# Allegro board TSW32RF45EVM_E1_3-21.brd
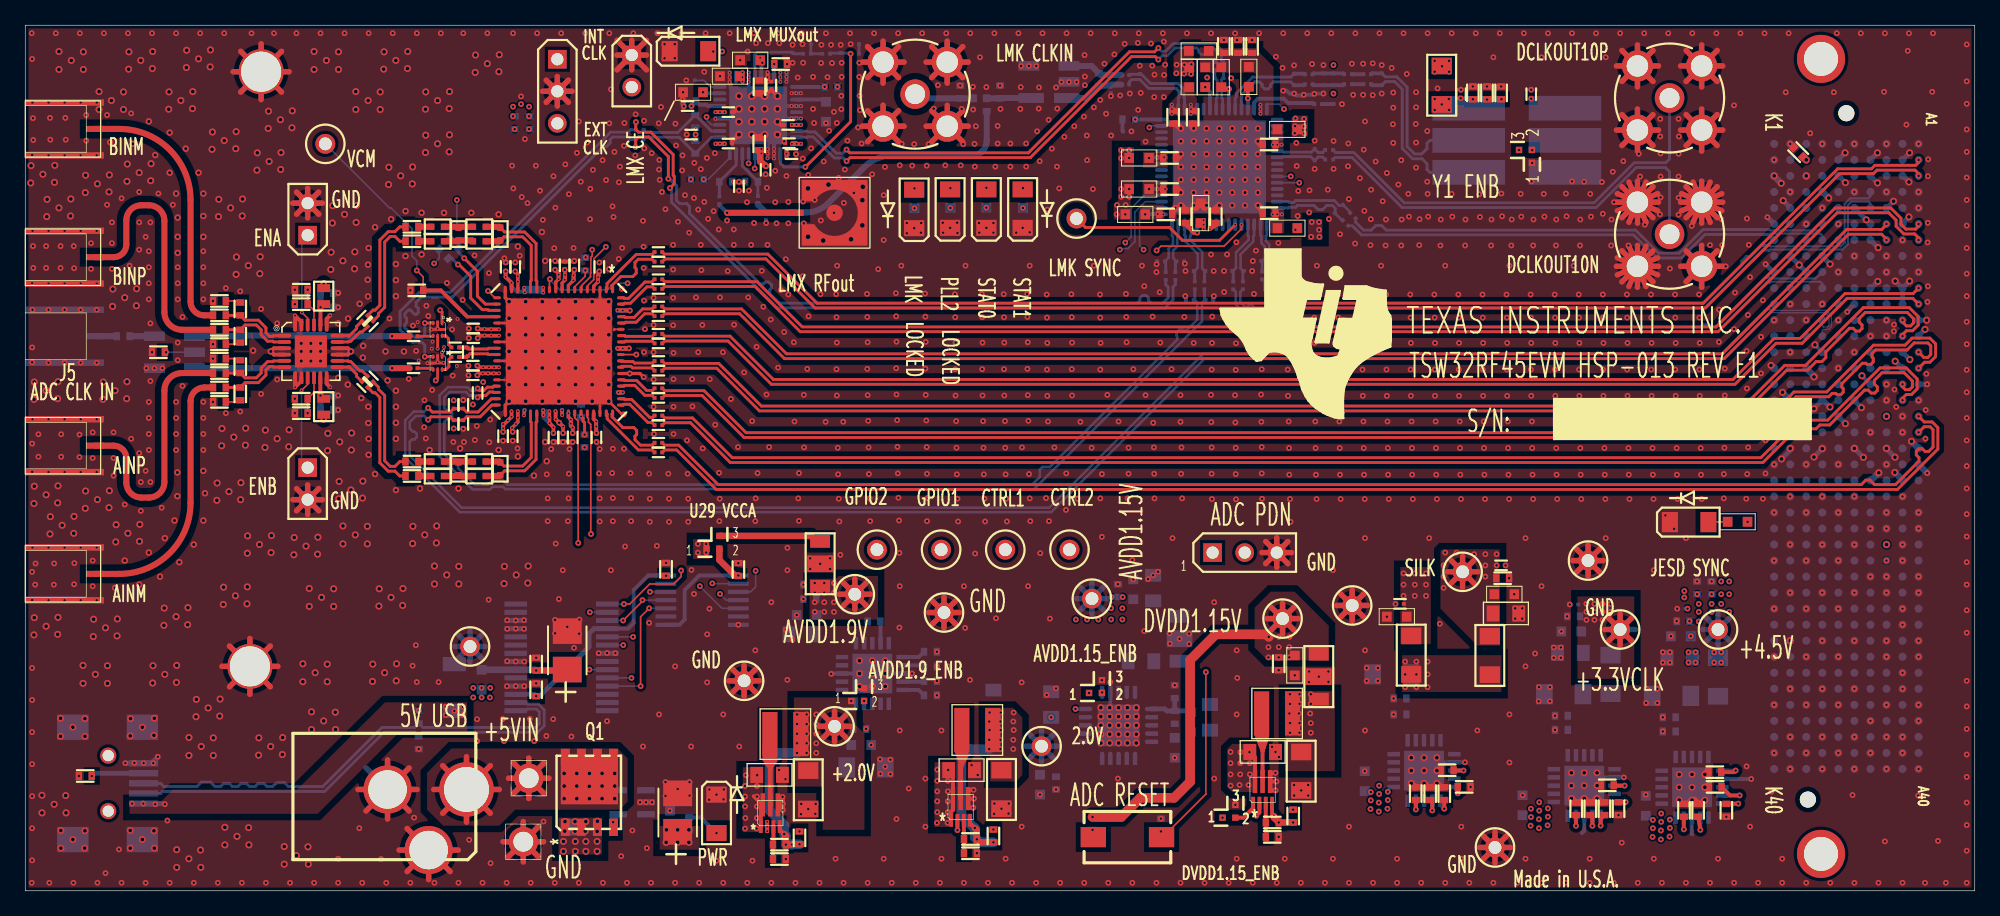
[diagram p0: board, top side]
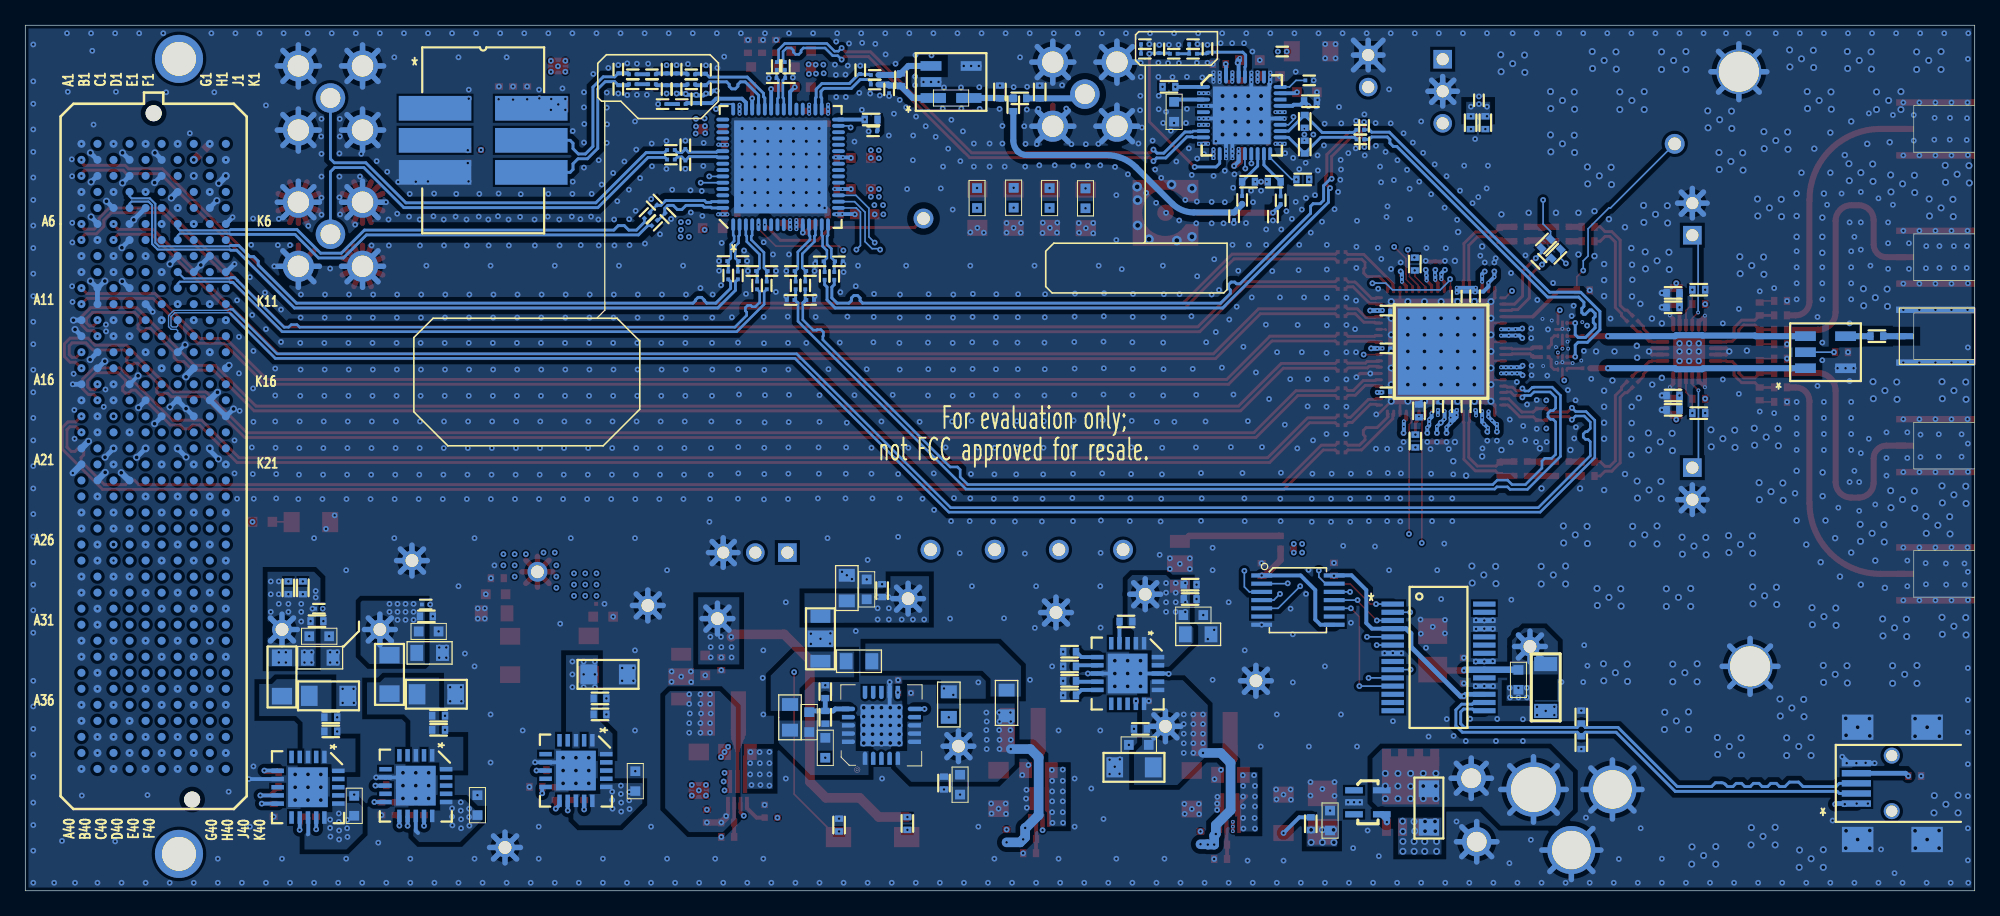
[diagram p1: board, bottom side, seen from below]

Outline 154.31 x 68.58 mm; copper layers: TOP, L2_GND, L3_PWR, L4_SIG, L5_GND, L6_PWR, L7_GND, BOTTOM. Coordinates in mm from the lower left corner of the outline.
Outline path: 0,68.58 0,0 154.31,0 154.31,68.58 0,68.58

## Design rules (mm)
net group CLK: nets CLKM CLKP
net group CLK_LAO: nets CLK_LAO_0M CLK_LAO_0P
net group CLKIN1: nets CLKIN1_N CLKIN1_P
net group DA0: nets DA0M DA0P
net group DA1: nets DA1M DA1P
net group DA2: nets DA2M DA2P
net group DA3: nets DA3M DA3P
net group DB0: nets DB0M DB0P
net group DB1: nets DB1M DB1P
net group DB2: nets DB2M DB2P
net group DB3: nets DB3M DB3P
net group DIFFPAIR9: nets GTXCLKM GTXCLKP
net group DP1: nets N19886018 N19886020
net group DP2: nets CLKLA_0M CLKLA_0P
net group DP3: nets N20235277 N20235286
net group DP4: nets N20015888 N20015984
net group DP5: nets SYSREF+ SYSREF-
net group DP6: nets AINM AINP
net group DP7: nets BINM BINP
net group DP8: nets LMX_OSCM LMX_OSCP
net group DP9: nets DA0_M DA0_P
net group DP10: nets DA1_M DA1_P
net group DP11: nets DA2_M DA2_P
net group DP12: nets DA3_M DA3_P
net group DP13: nets DB0_M DB0_P
net group DP14: nets DB1_M DB1_P
net group DP15: nets DB2_M DB2_P
net group DP16: nets DB3_M DB3_P
net group DP17: nets JESD_SYSREFM JESD_SYSREFP
net group DP18: nets USBDM USBDP
net group DP19: nets LMX_CLKM LMX_CLKP
net group FPGA_JESD_CLK: nets FPGA_JESD_CLKM FPGA_JESD_CLKP
net group FPGA_JESD_SYSREF: nets FPGA_JESD_SYSREFM FPGA_JESD_SYSREFP
net group INA: nets INA+ INA-
net group INB: nets INB+ INB-
net group OSC: nets OSCN OSCP
net group OSCIN: nets OSCINN OSCINP
net group OSCOUT: nets OSCOUTN OSCOUTP
net group OUTA: nets OUTA+ OUTA-
net group OUTB: nets OUTB+ OUTB-
net group SYNCB: nets SYNCBM SYNCBP
net group SYSREF: nets SYSREFM SYSREFP
net group TA: nets TA+ TA-
net group TB: nets TB+ TB-
net group Y2: nets Y2_N Y2_P

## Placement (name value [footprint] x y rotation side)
C1  .01uF  [0402]  21.84 47.62 0 bottom
C2  3.9pF  [0402_CUSTOM]  34.29 33.44 90 top
C3  1.6pF  [0402_CUSTOM]  37.59 33.44 90 top
C4  .1uF  [0402]  15.37 41.02 0 top
C5  .1uF  [0402]  15.37 39.88 0 top
C6  1.6pF  [0402_CUSTOM]  37.59 52.03 270 top
C8  .1uF  [0201]  91.03 48.72 270 bottom
C9  .1uF  [0201]  90.27 48.72 270 bottom
C10  3.9pF  [0402_CUSTOM]  34.29 52.03 270 top
C11  2200pF  [0402]  132.33 24 90 bottom
C12  .01uF  [0402]  133.48 24 90 bottom
C13  .1uF  [0201]  50.11 41.21 0 top
C14  .1uF  [0201]  50.11 41.97 0 top
C15  .1uF  [0201]  50.11 39.05 0 top
C16  .1uF  [0201]  50.11 39.81 0 top
C17  .1uF  [0201]  50.11 36.89 0 top
C18  .1uF  [0201]  50.11 37.66 0 top
C19  .1uF  [0201]  50.11 34.73 0 top
C20  .1uF  [0201]  50.11 35.5 0 top
C21  .1uF  [0201]  50.11 44.13 0 top
C22  .1uF  [0201]  50.11 43.37 0 top
C23  .1uF  [0201]  50.11 46.29 0 top
C24  .1uF  [0201]  50.11 45.53 0 top
C25  2200pF  [0402]  23.88 47.37 0 bottom
C26  .1uF  [0201]  50.11 48.45 0 top
C27  .1uF  [0201]  50.11 47.69 0 top
C28  .01uF  [0402]  7.75 43.94 0 bottom
C29  .01uF  [0402]  23.88 46.23 0 bottom
C30  .1uF  [0201]  50.11 50.61 0 top
C31  .1uF  [0201]  50.11 49.85 0 top
C32  2200pF  [0402]  23.88 39.24 0 bottom
C33  .1uF  [0402]  10.54 42.67 180 top
C34  .01uF  [0402]  23.88 38.1 0 bottom
C35  10uF  [0603]  128.27 6.73 90 bottom
C36  1uF  [0402]  131.29 6.38 90 top
C37  .1uF  [0201]  42.7 49.56 90 top
C38  .1uF  [0201]  41 47.09 270 bottom
C39  .1uF  [0201]  39.55 47.12 270 bottom
C40  .1uF  [0201]  38.02 49.43 90 top
C41  .1uF  [0201]  35.46 43.79 180 top
C42  .1uF  [0201]  35.43 41.61 180 top
C43  .1uF  [0201]  37.82 36.02 270 top
C44  .1uF  [0201]  39.52 38.38 90 bottom
C45  .1uF  [0201]  41 38.38 90 bottom
C46  .1uF  [0201]  41.81 35.92 270 top
C47  .1uF  [0201]  42.47 38.38 90 bottom
C48  .1uF  [0201]  41.94 49.56 90 top
C49  .1uF  [0201]  38.79 49.43 90 top
C50  .01uF  [0201]  35.46 44.55 180 top
C51  .01uF  [0201]  35.43 40.84 180 top
C52  .1uF  [0201]  38.58 36.02 270 top
C53  .1uF  [0201]  42.57 35.92 270 top
C54  .1uF  [0201]  45.44 49.43 90 top
C55  .1uF  [0201]  43.46 49.56 90 top
C56  .1uF  [0201]  43.33 35.92 270 top
C57  .1uF  [0201]  45.21 35.92 270 top
C58  .1uF  [0201]  46.58 39.5 180 bottom
C59  .1uF  [0201]  46.58 42.98 180 bottom
C60  .1uF  [0201]  46.58 45.97 180 bottom
C61  .1uF  [0402]  30.99 47.57 180 top
C62  .1uF  [0402]  130.12 12.62 180 bottom
C63  1uF  [0402]  130.12 13.74 180 bottom
C64  47uF  [1206]  130.3 15.44 180 bottom
C65  33uF  [0805]  130.96 18.47 180 bottom
C66  10uF  [0603]  131.04 20.17 180 bottom
C67  .1uF  [0201]  98.66 48.75 270 bottom
C68  .1uF  [0201]  119.2 63.12 90 top
C69  .1uF  [0201]  97.9 48.75 270 bottom
C70  .68uF  [0402]  87.35 61.11 180 bottom
C71  3900pF  [0201]  102.34 62.33 0 bottom
C72  47pF  [0201]  101.19 62.71 90 bottom
C73  .01uF  [0201]  87.07 63.88 0 bottom
C74  .01uF  [0201]  87.07 64.64 0 bottom
C75  .1uF  [0201]  88.21 65.02 270 bottom
C76  .1uF  [0402]  131.22 21.36 180 bottom
C77  .1uF  [0201]  113.64 63.12 270 top
C78  100pF  [0402]  114.58 63.22 270 top
C79  2200pF  [0402]  115.7 63.22 270 top
C80  10pF  [0402]  116.81 63.22 270 top
C81  .1uF  [0201]  104.7 64.69 180 bottom
C82  .1uF  [0201]  101.59 64.69 180 bottom
C83  .1uF  [0201]  100.43 65.05 270 bottom
C84  .1uF  [0201]  104.7 63.91 180 bottom
C85  .1uF  [0201]  101.59 63.9 180 bottom
C86  12pF  [0201]  100.43 63.52 90 bottom
C87  1uF  [0402]  90.86 61.29 90 top
C88  .1uF  [0402]  94.23 53.42 270 top
C89  0.01uF  [0402]  92.41 61.29 90 top
C90  1uF  [0402]  90.27 53.59 180 top
C91  1uF  [0402]  90.58 55.6 180 top
C92  1uF  [0402]  90.58 58.06 180 top
C93  1uF  [0402]  94.87 66.9 270 top
C94  .1uF  [0402]  95.99 66.9 270 top
C95  0.01uF  [0402]  97.1 66.9 270 top
C96  .1uF  [0402]  91.85 53.42 90 top
C97  10uF  [0603]  93.04 53.7 90 top
C98  1uF  [0402]  98.45 59.13 0 top
C99  1uF  [0402]  98.45 53.7 0 top
C100  .01uF  [0201]  131.06 22.35 180 bottom
C101  4.7uF  [TANT_B]  42.9 19.05 90 top
C102  .1uF  [0402]  40.44 17.96 90 top
C103  47pF  [0402]  31.14 11.73 270 bottom
C104  47pF  [0402]  31.14 13.77 90 bottom
C105  .1uF  [0402]  40.44 15.93 90 top
C110  .1uF  [0402]  15.37 44.45 0 top
C111  .1uF  [0402]  15.37 45.59 0 top
C114  .01uF  [0402]  21.84 37.85 0 bottom
C121  10uF  [0805]  74.11 9.56 0 top
C122  1uF  [0402]  81.58 8.53 270 bottom
C126  2.2uF  [0603]  80.31 8.41 270 bottom
C156  10uF  [0603]  118.52 6.78 90 bottom
C157  .1uF  [0402]  121.59 12.75 180 bottom
C158  1uF  [0402]  121.59 13.87 180 bottom
C159  47uF  [1206]  121.77 15.57 180 bottom
C160  33uF  [0805]  122.3 18.85 180 bottom
C161  10uF  [0603]  122.38 20.55 180 bottom
C162  .01uF  [0201]  122.61 22.68 180 bottom
C163  .1uF  [0402]  122.56 21.74 180 bottom
C166  1uF  [0402]  122.76 6.5 90 top
C170  .1uF  [0201]  103.2 58.7 0 bottom
C171  .1uF  [0201]  103.2 57.94 0 bottom
C172  47uF  [TANT_B]  51.64 6.2 90 top
C173  10uF  [0603]  51.03 5.56 90 bottom
C183  10uF  [0805]  58.91 9.18 0 top
C184  22uF  [1206]  61.98 8 270 top
C185  33uF  [0805]  61.47 20.32 180 bottom
C186  10uF  [0603]  61.85 21.84 180 bottom
C187  1uF  [0402]  62.1 23.11 180 bottom
C188  .1uF  [0402]  62.1 24.26 180 bottom
C189  47uF  [1206]  66.55 9.78 0 bottom
C190  10uF  [0603]  66.17 11.56 0 bottom
C191  1uF  [0402]  66.04 12.83 0 bottom
C193  .47uF  [0603]  92.25 13.36 90 bottom
C194  33uF  [0805]  89.28 23.98 90 bottom
C195  10uF  [0603]  87.7 23.88 90 bottom
C196  1uF  [0402]  86.48 23.78 90 bottom
C197  10uF  [0603]  90.98 11.33 270 bottom
C198  4.7uF  [0805]  81.2 14.76 90 bottom
C203  10uF  [0805]  97.94 11 0 top
C204  22uF  [1206]  100.99 9.47 270 top
C368  .1uF  [0402]  56.45 25.45 90 top
C369  .1uF  [0402]  50.72 25.47 270 top
C372  .1uF  [0201]  30.73 43.94 0 top
C373  .1uF  [0201]  30.73 41.4 0 top
C376  22uF  [1206]  77.27 8.03 270 top
C377  10uF  [0603]  100.48 17.86 270 top
C378  1uF  [0402]  99.21 17.98 270 top
C379  10uF  [0603]  108.56 21.72 180 top
C380  .01uF  [0201]  108.81 22.73 180 top
C381  10uF  [0603]  117.07 23.5 0 top
C382  .1uF  [0402]  116.94 24.77 0 top
C383  .01uF  [0201]  116.81 25.78 0 top
C384  33uF  [0805]  117.2 21.97 0 top
C385  47uF  [1206]  108.18 17.14 180 bottom
C386  10uF  [0603]  106.02 8.69 90 bottom
C387  1uF  [0402]  110.06 7.7 90 top
C388  .1uF  [0402]  108.81 13.97 180 bottom
C389  1uF  [0402]  108.81 15.24 180 bottom
C390  .1uF  [0201]  55.65 61.7 180 top
C391  .1uF  [0201]  60.45 59.23 0 top
C392  .1uF  [0201]  60.38 60.68 180 top
C393  .1uF  [0201]  60.66 58.37 0 top
C394  .047uF  [0201]  65.68 66.32 0 bottom
C395  560pF  [0201]  64.54 66.68 90 bottom
C396  .1uF  [0201]  58.6 57.12 270 top
C397  .1uF  [0201]  55.65 59.21 0 top
C398  1uF  [0402]  58.09 59.18 270 top
C399  .1uF  [0201]  52.43 62.18 180 top
C400  1uF  [0402]  52.58 62.56 0 bottom
C401  .1uF  [0201]  59.05 63.8 270 top
C402  1uF  [0402]  58.12 63.7 90 top
C403  10uF  [0603]  63.37 61.72 90 bottom
C404  1uF  [0402]  59.79 65.51 180 top
C405  10uF  [0603]  52.86 63.27 0 top
C406  10uF  [0603]  57.38 65.81 0 top
C407  10uF  [0603]  55.78 64.54 0 top
C408  100pF  [0201]  52.7 59.92 180 top
C409  100pF  [0201]  48.64 60.3 180 bottom
C410  100pF  [0201]  48.62 59.54 180 bottom
C411  100pF  [0201]  56.49 55.83 270 top
C412  100pF  [0201]  57.99 54.74 270 bottom
C413  100pF  [0201]  54.94 54.71 270 bottom
C418  .1uF  [0201]  94.18 65.35 90 bottom
C419  .1uF  [0201]  94.82 65.35 90 bottom
C420  6800pF  [0201]  61.87 67.08 180 bottom
C421  6800pF  [0201]  60.73 66.7 90 bottom
C428  .1uF  [0201]  39.24 62.64 90 bottom
C429  .1uF  [0201]  34.04 43.05 0 top
C430  .1uF  [0201]  34.04 42.29 0 top
C431  .1uF  [0201]  48.34 60.6 90 bottom
C432  .1uF  [0201]  48.31 59.23 270 bottom
C433  .01uF  [0402]  30.61 52.61 0 top
C434  .01uF  [0402]  30.61 51.46 0 top
C435  .01uF  [0402]  30.61 32.86 0 top
C436  .01uF  [0402]  30.61 34.01 0 top
C437  .01uF  [0402]  15.37 43.31 0 top
C438  .01uF  [0402]  15.37 46.74 0 top
C439  .01uF  [0402]  15.37 38.73 0 top
C440  .01uF  [0402]  15.37 42.16 0 top
D1  LED GREEN  [LED_1206]  76.07 54.05 270 top
D2  LED GREEN  [LED_1206]  78.94 54.05 270 top
D3  LED GREEN  [LED_1206]  70.36 54.03 270 top
D4  LED GREEN  [LED_1206]  73.2 54.05 270 top
D5  LED GREEN  [LED_1206]  131.7 29.21 180 top
D6  LED GREEN  [LED_1206]  54.71 6.1 90 top
D7  LED GREEN  [LED_1206]  52.53 66.52 180 top
F1  FUSE 10A 63V FAST  [1206]  43.21 6.55 270 bottom
FB1  120 OHM @ 100MHz  [1206]  112.12 63.83 90 top
FB2  120 OHM  [0603]  92.13 64.47 270 top
FB3  120 OHM  [0603]  87.86 53.59 0 top
FB4  120 OHM  [0603]  88.16 55.6 0 top
FB5  120 OHM  [0603]  88.16 58.06 0 top
FB6  120 OHM  [0603]  92.89 66.55 0 top
FB7  120 OHM  [0603]  93.4 64.47 270 top
FB8  120 OHM  [0603]  94.67 64.47 270 top
FB9  120 OHM  [0603]  96.85 64.49 270 top
FB10  120 OHM  [0603]  99.89 60.33 180 top
FB11  120 OHM  [0603]  99.9 52.5 180 top
FB12  1K OHM @ 100MHz  [1806]  33.96 16.1 270 bottom
FB13  120 OHM @ 100MHz  [1206]  133.99 16.94 90 bottom
FB14  120 OHM @ 100MHz  [1206]  109.7 18.67 90 top
FB15  120 OHM @ 100MHz  [1206]  115.93 18.64 90 top
FB16  120 OHM @ 100MHz  [1206]  125.48 17.14 90 bottom
FB17  27uF  [1206_BEAD_NFM31P]  91.36 19.96 90 bottom
FB19  27uF  [1206_BEAD_NFM31P]  102.39 16.97 90 top
FB20  27uF  [1206_BEAD_NFM31P]  62.92 25.91 90 top
HS1  COPPER PIN FIN HEAT SINK  [HEATSINK_270X270]  42.24 42.72 180 bottom
J1  CONN, MMSP-3805-LD-EDGE  [SMA-MSSP-4848-EDGE_MICRO]  5.21 35.27 0 top
J2  CONN, MMSP-3805-LD-EDGE  [SMA-MSSP-4848-EDGE_MICRO]  5.21 25.11 0 top
J3  CONN, MMSP-3805-LD-EDGE  [SMA-MSSP-4848-EDGE_MICRO]  5.21 50.2 0 top
J4  CONN, MMSP-3805-LD-EDGE  [SMA-MSSP-4848-EDGE_MICRO]  5.21 60.36 0 top
J5  CONN, MMSP-3805-LD-EDGE  [SMA-MSSP-4848-EDGE_MICRO]  5.21 43.94 0 bottom
J6  SMP_PCB_SMT  [SMP_B120]  64.06 53.72 270 top
J7  SMA_THVT_REC  [SMA_THVT_312X312]  70.43 63.12 0 top
J8  CONN, JACK, PWR, MINI, R/A, TH  [CON_RAPC722_JACK_THVT_3]  31.8 8.03 270 top
J9  SMA_THVT_REC  [SMA_THVT_312X312]  130.15 52.02 0 top
J10  CON, SMVT, HS, FIELD ARRAY, 400POS, MALE  [CON_SMVT_40X10_SEAM_MTG]  144.14 34.42 90 bottom
J11  CONN, USB MINI AB, SMT  [CON_SMRT_USBMNE20_F]  5.92 8.51 0 bottom
J13  SMA_THVT_REC  [SMA_THVT_312X312]  130.15 62.81 0 top
JP1  HDR, THVT, 3POS  [HDR_THVT_1X3_100_M]  93.98 26.8 90 top
JP2  HEADER_1x2_100_430L  [HDR_THVT_1X2_100_M]  48.01 66.22 0 top
JP3  HDR, THVT, 3POS  [HDR_THVT_1X3_100_M]  42.11 65.89 0 top
JP4  JUMPER_1X2_100  [HDR_THVT_1X2_100_M]  22.35 51.94 180 top
JP5  JUMPER_1X2_100  [HDR_THVT_1X2_100_M]  22.35 33.53 0 top
L1  .47uH  [IND_SM_XFL4015]  60.17 12.41 0 top
L2  .47uH  [IND_SM_XFL4015]  75.36 12.74 0 top
L3  .47uH  [IND_SM_XFL4015]  99.09 14.05 0 top
L4  5.1nH  [IND_0603]  23.62 47.12 270 top
L5  2nH  [0402_CUSTOM]  32.64 32.86 0 top
L6  2nH  [0402_CUSTOM]  32.64 34.01 0 top
L7  4.9nH  [0402_CUSTOM]  35.94 32.86 0 top
L8  2nH  [0402_CUSTOM]  32.64 52.61 0 top
L9  2nH  [0402_CUSTOM]  32.64 51.46 0 top
L11  4.9nH  [0402_CUSTOM]  35.94 52.61 0 top
L12  4.9nH  [0402_CUSTOM]  35.94 51.46 0 top
L13  4.9nH  [0402_CUSTOM]  35.94 34.01 0 top
L14  5.1nH  [IND_0603]  23.62 38.35 90 top
MT1  STANDOFF, FEMALE, 4-40 X 1 3/16", AL  [MFG125_PLATED]  18.67 64.9 0 top
MT2  STANDOFF, FEMALE, 4-40 X 1 3/16", AL  [MFG125_PLATED]  17.78 17.78 0 top
NOREF  -  []  0 0 90 top
NOREF#2  -  []  242.57 11.43 0 top
NOREF#3  -  []  116.51 3.91 0 top
NOREF#4  -  []  0 58.52 90 top
NOREF#5  -  []  494.89 162.18 0 top
NOREF#6  -  []  0 0 90 top
NOREF#7  -  []  101.19 -25.65 0 top
NOREF#8  -  []  0 68.58 0 top
NOREF#9  -  []  0 0 90 top
NOREF#10  -  []  10.77 37.72 0 top
NOREF#11  -  []  0 0 90 top
NOREF#12  -  []  0 0 0 top
NOREF#13  -  []  726.8 113.13 0 top
NOREF#14  -  []  161.32 -26.49 0 top
NOREF#15  -  []  -106.07 -149.22 0 top
NOREF#16  -  []  0 0 0 top
NOREF#17  -  []  145.54 -11.73 0 top
NOREF#18  -  []  314.12 44.43 0 top
NOREF#19  -  []  -95.38 325.27 0 top
NOREF#20  -  []  0 0 90 top
NOREF#21  -  []  0 0 90 top
NOREF#22  -  []  100.33 -4.45 180 bottom
Q1  CSD18532Q5  [SON_Q5B_8]  44.65 7.8 90 top
R1  90.9  [0402]  17.02 41.53 90 top
R2  4.99k  [0402]  21.84 46.48 0 top
R3  4.99k  [0402]  21.84 47.62 180 top
R4  24.9  [0201]  26.87 40.11 315 top
R5  24.9  [0201]  27.31 40.55 315 top
R6  90.9  [0402]  17.02 43.94 270 top
R7  4.99k  [0402]  21.84 38.99 0 top
R8  4.99k  [0402]  21.84 37.85 180 top
R9  24.9  [0201]  26.87 45.36 45 top
R10  24.9  [0201]  27.31 44.92 45 top
R11  0  [0402]  132.41 6.38 270 top
R12  0  [0402]  134.65 6.38 90 top
R13  0  [0402]  133.76 8.23 0 top
R14  0  [0402]  133.73 9.4 0 top
R26  100  [0201]  35.03 42.68 90 top
R29  100  [0201]  35.8 39.44 90 top
R31  0  [0402]  44.27 35.64 90 bottom
R32  10K  [0402]  43.99 38.02 90 bottom
R33  1K  [0402]  84.48 5.33 270 bottom
R34  1K  [0402]  44.32 49.66 270 bottom
R35  10K  [0402]  89.89 5.21 90 bottom
R40  100  [0201]  34.5 49.86 45 bottom
R47  39K  [0201]  87.2 60.17 0 bottom
R48  0  [0201]  96.38 47.97 270 bottom
R49  0  [0201]  95.62 47.97 270 bottom
R50  240  [0201]  95.24 49.11 180 bottom
R51  240  [0201]  96.76 49.11 0 bottom
R52  240  [0201]  97.52 49.9 180 bottom
R53  240  [0201]  99.05 49.9 0 bottom
R54  620  [0201]  103.86 62.33 0 bottom
R55  49.9  [0201]  85.93 63.5 270 bottom
R56  0  [0603]  81.03 62.81 0 bottom
R57  18  [0402]  75.58 62.79 0 bottom
R58  292  [0402]  74.01 63.29 90 bottom
R59  292  [0402]  77.16 63.29 90 bottom
R60  100  [0402]  84.99 64.26 90 bottom
R63  120  [0201]  91.43 49.87 0 bottom
R64  120  [0201]  89.9 49.87 180 bottom
R65  100  [0201]  93.33 47.97 270 bottom
R66  100  [0201]  92.57 47.97 270 bottom
R67  200  [0201]  93.71 49.11 0 bottom
R68  200  [0201]  92.19 49.11 180 bottom
R69  100  [0201]  92.18 46.81 180 bottom
R70  100  [0201]  93.73 46.81 0 bottom
R71  130  [0201]  103.54 65.07 270 bottom
R72  100  [0201]  106.22 64.69 180 bottom
R73  82  [0201]  107.37 65.07 90 bottom
R74  49.9  [0201]  102.75 65.07 90 bottom
R75  0  [0201]  105.08 53.49 315 bottom
R76  130  [0201]  103.54 63.52 90 bottom
R77  240  [0201]  104.51 54.56 45 bottom
R78  240  [0201]  103.44 53.48 225 bottom
R79  0  [0201]  104.5 52.91 315 bottom
R80  100  [0201]  106.22 63.91 180 bottom
R81  82  [0201]  107.37 63.53 270 bottom
R82  49.9  [0201]  102.75 63.52 270 bottom
R84  750  [0603]  76.07 54.91 270 bottom
R85  750  [0603]  78.97 54.89 270 bottom
R86  750  [0603]  70.38 54.86 270 bottom
R87  750  [0603]  73.23 54.89 270 bottom
R88  750  [0603]  135.53 29.24 0 top
R89  0  [0402]  140.34 58.52 135 top
R95  0  [0603]  36.12 16.71 90 bottom
R96  0  [0402]  4.75 9.09 0 top
R124  0  [0402]  123.88 6.5 270 top
R125  0  [0402]  124.99 6.5 270 top
R126  0  [0402]  126.11 6.5 90 top
R127  0  [0402]  125.22 8.36 0 top
R132  287K  [0402]  59.69 3.66 180 top
R133  1K  [0402]  52.55 5.31 90 bottom
R134  162K  [0402]  59.69 2.51 0 top
R136  1M  [0402]  61.28 4.19 90 top
R137  36.5K  [0402]  67.18 21.34 0 bottom
R138  0  [0402]  71.65 18.94 180 bottom
R139  0  [0402]  71.65 17.77 180 bottom
R140  0  [0402]  71.65 16.63 180 bottom
R141  0  [0402]  71.65 15.49 180 bottom
R143  2.4K  [0402]  90.98 13.74 90 bottom
R145  4.75K  [0402]  90.98 15.77 90 bottom
R146  82K  [0402]  98.7 5.41 180 top
R147  162K  [0402]  98.7 4.27 0 top
R148  1M  [0402]  100.36 5.92 90 top
R151  240  [0201]  102.06 57.56 270 bottom
R152  240  [0201]  102.06 59.08 90 bottom
R153  1M  [0402]  76.63 4.34 90 top
R154  124K  [0402]  74.81 4.1 180 top
R155  162K  [0402]  74.81 2.97 0 top
R157  0  [0805]  76.63 14.88 270 bottom
R158  0  [0805]  93.78 13.74 270 bottom
R159  0  [0805]  88.32 18.19 180 bottom
R164  0  [0402]  33.12 50.47 315 bottom
R165  0  [0402]  33.93 51.28 315 bottom
R166  182  [0201]  33.91 36.98 90 top
R167  182  [0201]  33.91 38.51 270 top
R168  68  [0201]  34.67 36.98 270 top
R169  68  [0201]  34.67 38.51 90 top
R170  0  [0402]  111.2 7.7 270 top
R171  0  [0402]  112.55 9.55 0 top
R172  0  [0402]  112.32 7.7 270 top
R173  0  [0402]  113.89 8.23 180 top
R174  150  [0201]  65.68 67.08 180 bottom
R175  49.9  [0402]  53.04 60.96 270 bottom
R176  49.9  [0402]  53.04 58.93 90 bottom
R177  49.9  [0402]  57.48 56.18 180 bottom
R178  49.9  [0402]  55.45 56.18 0 bottom
R179  680  [0201]  52.68 64.21 0 bottom
R180  240  [0201]  95.15 64.39 0 bottom
R181  240  [0201]  93.85 64.39 180 bottom
R182  0  [0201]  63.4 66.32 180 bottom
R183  12  [0201]  61.87 66.32 180 bottom
R184  0  [0402]  53.19 56.36 180 bottom
R185  680  [0201]  54.81 66.5 0 bottom
R186  12k  [0402]  63.78 63.7 0 bottom
R187  49.9  [0201]  55.55 53.42 90 bottom
R188  10K  [0402]  38.73 60.86 270 bottom
R189  10K  [0402]  39.9 60.86 270 bottom
R191  0  [0402]  76.1 62.28 270 bottom
R192  49.9  [0201]  58.62 53.44 90 bottom
R193  80.6  [0402]  17.02 46.1 90 top
R194  80.6  [0402]  17.02 39.37 270 top
SJP1  SOLDER JUMPER, 0402  [SMD_JUMPER_L_0402]  119.25 58.19 90 top
SJP2  SOLDER JUMPER, 0402  [SMD_JUMPER_L_0402]  65.89 15.04 0 top
SJP3  SOLDER JUMPER, 0402  [SMD_JUMPER_L_0402]  84.71 15.67 0 top
SJP4  SOLDER JUMPER, 0402  [SMD_JUMPER_L_0402]  95.28 5.79 0 top
SJP5  SOLDER JUMPER, 0402  [SMD_JUMPER_L_0402]  54.43 27.1 0 top
SW1  SWITCH, SMT, PUSHBUTTON  [SW_SMVT_SPST_EVQPJX_2]  87.24 4.25 0 top
T5  ETC1-1-13  [TFMR_5_150X150_50]  11.81 42.67 0 bottom
T6  TC1-1-13M+  [TFMR_5_150X150_50]  81.03 64.08 0 bottom
TP1  RED  [TP_THVT_060_RND]  133.99 20.7 0 top
TP2  RED  [TP_THVT_060_RND]  23.75 59.18 0 top
TP3  YELLOW  [TP_THVT_060_RND]  72.49 27.03 0 top
TP4  RED  [TP_THVT_060_RND]  35.2 19.35 0 top
TP5  RED  [TP_THVT_060_RND]  99.52 21.56 0 top
TP6  BLK  [TP_THVT_060_RND]  105.03 22.61 0 top
TP7  YELLOW  [TP_THVT_060_RND]  67.41 27.03 0 top
TP8  YELLOW  [TP_THVT_060_RND]  77.57 27.03 0 top
TP9  YELLOW  [TP_THVT_060_RND]  82.65 27.03 0 top
TP10  RED  [TP_THVT_060_RND]  113.77 25.27 0 top
TP11  BLK  [TP_THVT_060_RND]  116.33 3.43 0 top
TP12  RED  [TP_THVT_060_RND]  126.24 20.7 0 top
TP13  RED  [TP_THVT_060_RND]  80.44 11.46 0 top
TP14  BLK  [TP_THVT_060_RND]  56.9 16.64 0 top
TP15  RED  [TP_THVT_060_RND]  64.06 13.03 0 top
TP16  YELLOW  [TP_THVT_060_RND]  83.21 53.26 0 top
TP17  Testloop_Red  [TESTPOINT_62DIA]  39.85 8.92 0 top
TP18  Testloop_Black  [TESTPOINT_62DIA]  39.42 3.89 0 top
TP19  BLK  [TP_THVT_060_RND]  123.7 26.16 0 top
TP20  RED  [TP_THVT_060_RND]  65.66 23.5 0 top
TP21  BLK  [TP_THVT_060_RND]  72.72 22.05 0 top
TP22  RED  [TP_THVT_060_RND]  84.43 23.14 90 top
U1  ADC32RF45_72QFN  [QFN_72_10MMX10MM_0P50MM_PWRPAD]  42.24 42.74 270 top
U2  LMH3401  [QFN24_RGE_RTW_P5MM]  22.61 42.74 0 top
U3  LMK04828  [QFN_64_360X360_0P50MM_PWRPAD]  94.52 57.35 90 bottom
U4  TPS7A4700  [QFN_20_199X199_0P65MM]  131.93 8.2 270 bottom
U5  FT245RL  [SSOP_28_413X220_26]  42.44 18.49 180 bottom
U7  MASW_009444  [PDFN_6_P35MM]  32.64 41.81 270 top
U8  MASW_009444  [PDFN_6_P35MM]  32.64 44.48 270 top
U9  TPS7A4700  [QFN_20_199X199_0P65MM]  110.72 9.53 270 bottom
U10  LMX2582_LM2592  [QFN40_RTA_RTB_RHA]  58.01 61.44 180 bottom
U11  TPS62085  [QFN_RLT_7]  74.03 6.64 90 top
U12  TPS7A4700  [QFN_20_199X199_0P65MM]  123.39 8.33 270 bottom
U13  TXB0104  [TSSOP14]  53.57 23.03 180 bottom
U14  TPS62085  [QFN_RLT_7]  58.97 6.14 90 top
U15  TPS2400  [DBV5]  48.03 7.01 180 bottom
U16  TPS7A7200  [QFN_20_199X199_0P65MM]  67.05 17.21 270 bottom
U17  TPS74201/QFN20  [QFN20_RGW_P65PITCH]  86.54 13.11 90 bottom
U18  TPS62085  [QFN_RLT_7]  97.94 8 90 top
Y1  122.88MHz  [VCXO_6_CUSTOM]  118.06 59.46 180 bottom

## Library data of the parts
C1 C28 C72 C114 C437-C440 = CAP NP_0: tolerance: 5%
C2 C10 = CAP_0402_3.9pF
C3 C6 = CAP_0402_1.8pF
C4 C5 C110 C111 = CAP_0603_0.1uF_H: tolerance: 10%
C8 C9 C67 C69 C83 C87-C96 C98 C99 C170 C171 C368 C369 C390-C393 C396 C397 C399 C401 C418 C419 = CAPACITOR_NP_1: tolerance: 10%
C11 C25 C32 = CAP_0402_2200pF
C12 C29 C34 C433-C436 = CAP_0402_0.01uF
C13-C24 C26 C27 C30 C31 = CAP_0201_0.1uF: tolerance: 10%
C33 C62 C76 C157 C163 C188 C382 C388 = CAP0603: tolerance: 10%
C35 C121 C156 C173 C183 C187 C190 C196 C197 C203 C378 C386 C403 C405-C407 = CAP NP_1: tolerance: 10%
C36 C63 C68 C70 C71 C82 C85 C102 C105 C122 C158 C166 C191 C387 C389 C394 C395 C398 C400 C402 C404 C420 C421 = CAP NP_0: tolerance: 10%
C37-C49 C52-C61 C372 C373 C428-C432 = CAP0402_0: tolerance: 10%
C50 C51 = CAP0402_0: tolerance: +/-10%
C64 C159 C189 C385 = CAP NP_0: tolerance: 20%
C65 C160 C185 C186 C194 C195 C377 C384 = CAP0201_0: tolerance: 20%
C66 C161 C379 C381 = CAP0201_0: tolerance: 10%
C73 C74 = CAP_0402_0.01uF_H: tolerance: 10%
C75 = CAP_0402_0.1uF: tolerance: 10%
C77 C81 C84 = CAP_0402_0.1uF_H: tolerance: 10%
C78 C408-C413 = CAP_0603_100pF_H
C79 = CAP_0402_2200pF_H
C80 = CAP_0402_10pF_H
C86 = CAPACITOR_NP_1: tolerance: 2%
C97 = CAP NP_2: tolerance: 10%
C100 C162 C380 C383 = CAP0402_0: tolerance: 10V
C101 = CAP_TANT_B_4.7uF_10V
C103 C104 = CAP0603: tolerance: 1%
C126 = CAP_0603_2.2uF
C172 = CAP POL-B_0: tolerance: 10%
C184 C204 C376 = CAP: tolerance: 10%
C193 C198 = CAP_0603_.47uF
D1-D5 D7 = LED
D6 = LED_GREEN_0
F1 = FUSE_0
FB1-FB16 = FERRITE_BEAD_0402_H
FB17 FB19 FB20 = BEAD_NFM31P
HS1 = HEATSINK_270x270
J1-J5 = CON_LD_EDGE_MMSP_3805_M
J6 = SMP_PLUG_SMT
J7 J9 J13 = SMA-THVT_142-0701-201_REC
J8 = CONN JACK PWR
J10 = CON_SMVT_40X10_ASP-134487-01
J11 = USB_MINI_AB_MNE20-5G5P10
JP1 JP3 SJP1-SJP5 = SMD_JUMPER_1x3
JP2 = HDR_2x1_100
JP4 JP5 = JUMPER_1X2_100
L1-L3 = CHOKE
L4 L14 = IND_0603_H_0
L5-L9 L11-L13 = IND_0402_H_0
MT1 MT2 = MOUNTING_HOLE
Q1 = CSD18532Q5B
R1 R6 R166-R169 R193 R194 = Res_0402_49.9
R2 R3 R7 R8 = Res_0402_4.99K
R4 R5 R9 R10 R72 R80 = Res_0402_100_H
R11-R14 R124-R127 R138-R141 R170-R173 = R: tolerance: 5%
R26 R29 = Res_0201_200_H: tolerance: 1%
R31 = Res_0402_Zero_DNI
R32 R33 R35 R47 R54 R174 R188 R189 = R_1: tolerance: 1%
R34 = RES0603: tolerance: 1%
R40 = Res_0201_H: tolerance: 1%
R48 R49 R65 R66 R75 R79 R157-R159 R182 = Res_0402_Zero_H_DNI
R50-R53 R63 R64 R67 R68 R77 R78 R151 R152 R180 R181 = Res_0402_249
R55 R175-R179 R185 R187 R192 = Res_0402_49.9: tolerance: 1%
R56 R95 = Res_0603_Zero_DNI
R57 R183 R186 = Res_0402_18
R58 R59 = Res_0402_270
R60 R69 R70 = Res_0603_100
R71 R73 R74 R76 R81 R82 = RESISTOR_0: tolerance: 1%
R84-R88 = RESISTOR_0
R89 = Res_0402_Zero
R96 R164 R165 R184 R191 = R
R132 R146 R154 = Res_0603_Zero_H
R133 = Res_0402_1k: tolerance: 1%
R134 R136 R147 R148 R153 R155 = R: tolerance: 1%
R137 = Res_0402_Zero_H
R143 = Res_0603_12.4k
R145 = Res_0603_10k
SW1 = SPST_EVQ-PJ
T5 = BALUN_ETC1-1-13
T6 = TFMR_5_TC1-1-13M+
TP1 TP3 TP7-TP10 TP12 TP16 TP20 TP22 = TESTPOINT_BLUE
TP2 TP4 = TESTPOINT_RED
TP5 TP13 TP15 = TESTLOOP_RED
TP6 TP11 TP14 TP19 TP21 = TESTPOINT_BLK
TP17 TP18 = TESTLOOP_BLACK
U1 = ADC32RF4X_72QFN
U2 = LMH3404
U3 = LMK04828
U4 U9 U12 = TPS7A4700
U5 = FT245RL
U7 U8 = RF_SWITCH_MASW_009444
U10 = LMX2582_LM2592
U11 U14 U18 = TPS62085/62086/62087
U13 = TXS0104E: Tolerance: ***; User Part Number: ***
U15 = TPS2400
U16 = TPS7A7300
U17 = TPS74201/QFN20
Y1 = OSC_SM_6_TCO-2100-SERIES_2

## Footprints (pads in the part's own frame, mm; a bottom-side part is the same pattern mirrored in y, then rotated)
0201
  rect 0.305x0.305 smd: 1(-0.305,0) 2(0.305,0)
0402
  rect 0.508x0.635 smd: 1(-0.508,0) 2(0.508,0)
0402_CUSTOM
  rect 0.508x0.508 smd: 1(-0.508,0) 2(0.508,0)
0603
  rect 0.762x0.787 smd: 1(-0.787,0) 2(0.787,0)
0805
  rect 1.016x1.27 smd: 1(-1.016,0) 2(1.016,0)
1206
  rect 1.321x1.6 smd: 1(-1.524,0) 2(1.524,0)
1206_BEAD_NFM31P
  rect 1.016x1.575 smd: 1(-1.778,0) 3(1.778,0)
  rect 1.321x2.032 smd: 2(0,0)
1806
  rect 1.118x1.829 smd: 1(-1.854,0) 2(1.854,0)
CON_RAPC722_JACK_THVT_3
  round 4.318 hole 3.556: 1(0,3.124)
  round 3.81 hole 3.048: 2(0,-3.124) 3(4.801,0.127)
CON_SMRT_USBMNE20_F
  round 1.27 hole 0.889 unplated: (0.65,-2.2) (0.65,2.2)
  rect 2.311x0.508 smd: 1(3.45,1.6) 2(3.45,0.8) 3(3.45,0) 4(3.45,-0.8) 5(3.45,-1.6)
  rect 2.489x2.007 smd: 6(-2.15,-4.45) 7(3.35,-4.45) 8(3.35,4.45) 9(-2.15,4.45)
CON_SMVT_40X10_SEAM_MTG
  round 3.81 hole 2.692: (-31.496,-2.007) (31.496,-2.007)
  round 1.27 hole 1.27 unplated: (-27.191,-3.048) (27.191,0)
  round 0.635 smd: A1(24.765,5.715) A2(23.495,5.715) A3(22.225,5.715) A4(20.955,5.715) A5(19.685,5.715) A6(18.415,5.715) A7(17.145,5.715) A8(15.875,5.715) A9(14.605,5.715) A10(13.335,5.715) A11(12.065,5.715) A12(10.795,5.715) A13(9.525,5.715) A14(8.255,5.715) A15(6.985,5.715) A16(5.715,5.715) A17(4.445,5.715) A18(3.175,5.715) A19(1.905,5.715) A20(0.635,5.715) A21(-0.635,5.715) A22(-1.905,5.715) A23(-3.175,5.715) A24(-4.445,5.715) A25(-5.715,5.715) A26(-6.985,5.715) A27(-8.255,5.715) A28(-9.525,5.715) A29(-10.795,5.715) A30(-12.065,5.715) A31(-13.335,5.715) A32(-14.605,5.715) A33(-15.875,5.715) A34(-17.145,5.715) A35(-18.415,5.715) A36(-19.685,5.715) A37(-20.955,5.715) A38(-22.225,5.715) A39(-23.495,5.715) A40(-24.765,5.715) B1(24.765,4.445) B2(23.495,4.445) B3(22.225,4.445) B4(20.955,4.445) B5(19.685,4.445) B6(18.415,4.445) B7(17.145,4.445) B8(15.875,4.445) B9(14.605,4.445) B10(13.335,4.445) B11(12.065,4.445) B12(10.795,4.445) B13(9.525,4.445) B14(8.255,4.445) B15(6.985,4.445) B16(5.715,4.445) B17(4.445,4.445) B18(3.175,4.445) B19(1.905,4.445) B20(0.635,4.445) B21(-0.635,4.445) B22(-1.905,4.445) B23(-3.175,4.445) B24(-4.445,4.445) B25(-5.715,4.445) B26(-6.985,4.445) B27(-8.255,4.445) B28(-9.525,4.445) B29(-10.795,4.445) B30(-12.065,4.445) B31(-13.335,4.445) B32(-14.605,4.445) B33(-15.875,4.445) B34(-17.145,4.445) B35(-18.415,4.445) B36(-19.685,4.445) B37(-20.955,4.445) B38(-22.225,4.445) B39(-23.495,4.445) B40(-24.765,4.445) C1(24.765,3.175) C2(23.495,3.175) C3(22.225,3.175) C4(20.955,3.175) C5(19.685,3.175) C6(18.415,3.175) C7(17.145,3.175) C8(15.875,3.175) C9(14.605,3.175) C10(13.335,3.175) C11(12.065,3.175) C12(10.795,3.175) C13(9.525,3.175) C14(8.255,3.175) C15(6.985,3.175) C16(5.715,3.175) C17(4.445,3.175) C18(3.175,3.175) C19(1.905,3.175) C20(0.635,3.175) C21(-0.635,3.175) C22(-1.905,3.175) C23(-3.175,3.175) C24(-4.445,3.175) C25(-5.715,3.175) C26(-6.985,3.175) C27(-8.255,3.175) C28(-9.525,3.175) C29(-10.795,3.175) C30(-12.065,3.175) C31(-13.335,3.175) C32(-14.605,3.175) C33(-15.875,3.175) C34(-17.145,3.175) C35(-18.415,3.175) C36(-19.685,3.175) C37(-20.955,3.175) C38(-22.225,3.175) C39(-23.495,3.175) C40(-24.765,3.175) D1(24.765,1.905) D2(23.495,1.905) D3(22.225,1.905) D4(20.955,1.905) D5(19.685,1.905) D6(18.415,1.905) D7(17.145,1.905) D8(15.875,1.905) D9(14.605,1.905) D10(13.335,1.905) D11(12.065,1.905) D12(10.795,1.905) D13(9.525,1.905) D14(8.255,1.905) D15(6.985,1.905) D16(5.715,1.905) D17(4.445,1.905) D18(3.175,1.905) D19(1.905,1.905) D20(0.635,1.905) D21(-0.635,1.905) D22(-1.905,1.905) D23(-3.175,1.905) D24(-4.445,1.905) D25(-5.715,1.905) D26(-6.985,1.905) D27(-8.255,1.905) D28(-9.525,1.905) D29(-10.795,1.905) D30(-12.065,1.905) D31(-13.335,1.905) D32(-14.605,1.905) D33(-15.875,1.905) D34(-17.145,1.905) D35(-18.415,1.905) D36(-19.685,1.905) D37(-20.955,1.905) D38(-22.225,1.905) D39(-23.495,1.905) D40(-24.765,1.905) E1(24.765,0.635) E2(23.495,0.635) E3(22.225,0.635) E4(20.955,0.635) E5(19.685,0.635) E6(18.415,0.635) E7(17.145,0.635) E8(15.875,0.635) E9(14.605,0.635) E10(13.335,0.635) E11(12.065,0.635) E12(10.795,0.635) E13(9.525,0.635) E14(8.255,0.635) E15(6.985,0.635) E16(5.715,0.635) E17(4.445,0.635) E18(3.175,0.635) E19(1.905,0.635) E20(0.635,0.635) E21(-0.635,0.635) E22(-1.905,0.635) E23(-3.175,0.635) E24(-4.445,0.635) E25(-5.715,0.635) E26(-6.985,0.635) E27(-8.255,0.635) E28(-9.525,0.635) E29(-10.795,0.635) E30(-12.065,0.635) E31(-13.335,0.635) E32(-14.605,0.635) E33(-15.875,0.635) E34(-17.145,0.635) E35(-18.415,0.635) E36(-19.685,0.635) E37(-20.955,0.635) E38(-22.225,0.635) E39(-23.495,0.635) E40(-24.765,0.635) F1(24.765,-0.635) F2(23.495,-0.635) F3(22.225,-0.635) F4(20.955,-0.635) F5(19.685,-0.635) F6(18.415,-0.635) F7(17.145,-0.635) F8(15.875,-0.635) F9(14.605,-0.635) F10(13.335,-0.635) F11(12.065,-0.635) F12(10.795,-0.635) F13(9.525,-0.635) F14(8.255,-0.635) F15(6.985,-0.635) F16(5.715,-0.635) F17(4.445,-0.635) F18(3.175,-0.635) F19(1.905,-0.635) F20(0.635,-0.635) F21(-0.635,-0.635) F22(-1.905,-0.635) F23(-3.175,-0.635) F24(-4.445,-0.635) F25(-5.715,-0.635) F26(-6.985,-0.635) F27(-8.255,-0.635) F28(-9.525,-0.635) F29(-10.795,-0.635) F30(-12.065,-0.635) F31(-13.335,-0.635) F32(-14.605,-0.635) F33(-15.875,-0.635) F34(-17.145,-0.635) F35(-18.415,-0.635) F36(-19.685,-0.635) F37(-20.955,-0.635) F38(-22.225,-0.635) F39(-23.495,-0.635) F40(-24.765,-0.635) G1(24.765,-1.905) G2(23.495,-1.905) G3(22.225,-1.905) G4(20.955,-1.905) G5(19.685,-1.905) G6(18.415,-1.905) G7(17.145,-1.905) G8(15.875,-1.905) G9(14.605,-1.905) G10(13.335,-1.905) G11(12.065,-1.905) G12(10.795,-1.905) G13(9.525,-1.905) G14(8.255,-1.905) G15(6.985,-1.905) G16(5.715,-1.905) G17(4.445,-1.905) G18(3.175,-1.905) G19(1.905,-1.905) G20(0.635,-1.905) G21(-0.635,-1.905) G22(-1.905,-1.905) G23(-3.175,-1.905) G24(-4.445,-1.905) G25(-5.715,-1.905) G26(-6.985,-1.905) G27(-8.255,-1.905) G28(-9.525,-1.905) G29(-10.795,-1.905) G30(-12.065,-1.905) G31(-13.335,-1.905) G32(-14.605,-1.905) G33(-15.875,-1.905) G34(-17.145,-1.905) G35(-18.415,-1.905) G36(-19.685,-1.905) G37(-20.955,-1.905) G38(-22.225,-1.905) G39(-23.495,-1.905) G40(-24.765,-1.905) H1(24.765,-3.175) H2(23.495,-3.175) H3(22.225,-3.175) H4(20.955,-3.175) H5(19.685,-3.175) H6(18.415,-3.175) H7(17.145,-3.175) H8(15.875,-3.175) H9(14.605,-3.175) H10(13.335,-3.175) H11(12.065,-3.175) H12(10.795,-3.175) H13(9.525,-3.175) H14(8.255,-3.175) H15(6.985,-3.175) H16(5.715,-3.175) H17(4.445,-3.175) H18(3.175,-3.175) H19(1.905,-3.175) H20(0.635,-3.175) H21(-0.635,-3.175) H22(-1.905,-3.175) H23(-3.175,-3.175) H24(-4.445,-3.175) H25(-5.715,-3.175) H26(-6.985,-3.175) H27(-8.255,-3.175) H28(-9.525,-3.175) H29(-10.795,-3.175) H30(-12.065,-3.175) H31(-13.335,-3.175) H32(-14.605,-3.175) H33(-15.875,-3.175) H34(-17.145,-3.175) H35(-18.415,-3.175) H36(-19.685,-3.175) H37(-20.955,-3.175) H38(-22.225,-3.175) H39(-23.495,-3.175) H40(-24.765,-3.175) J1(24.765,-4.445) J2(23.495,-4.445) J3(22.225,-4.445) J4(20.955,-4.445) J5(19.685,-4.445) J6(18.415,-4.445) J7(17.145,-4.445) J8(15.875,-4.445) J9(14.605,-4.445) J10(13.335,-4.445) J11(12.065,-4.445) J12(10.795,-4.445) J13(9.525,-4.445) J14(8.255,-4.445) J15(6.985,-4.445) J16(5.715,-4.445) J17(4.445,-4.445) J18(3.175,-4.445) J19(1.905,-4.445) J20(0.635,-4.445) J21(-0.635,-4.445) J22(-1.905,-4.445) J23(-3.175,-4.445) J24(-4.445,-4.445) J25(-5.715,-4.445) J26(-6.985,-4.445) J27(-8.255,-4.445) J28(-9.525,-4.445) J29(-10.795,-4.445) J30(-12.065,-4.445) J31(-13.335,-4.445) J32(-14.605,-4.445) J33(-15.875,-4.445) J34(-17.145,-4.445) J35(-18.415,-4.445) J36(-19.685,-4.445) J37(-20.955,-4.445) J38(-22.225,-4.445) J39(-23.495,-4.445) J40(-24.765,-4.445) K1(24.765,-5.715) K2(23.495,-5.715) K3(22.225,-5.715) K4(20.955,-5.715) K5(19.685,-5.715) K6(18.415,-5.715) K7(17.145,-5.715) K8(15.875,-5.715) K9(14.605,-5.715) K10(13.335,-5.715) K11(12.065,-5.715) K12(10.795,-5.715) K13(9.525,-5.715) K14(8.255,-5.715) K15(6.985,-5.715) K16(5.715,-5.715) K17(4.445,-5.715) K18(3.175,-5.715) K19(1.905,-5.715) K20(0.635,-5.715) K21(-0.635,-5.715) K22(-1.905,-5.715) K23(-3.175,-5.715) K24(-4.445,-5.715) K25(-5.715,-5.715) K26(-6.985,-5.715) K27(-8.255,-5.715) K28(-9.525,-5.715) K29(-10.795,-5.715) K30(-12.065,-5.715) K31(-13.335,-5.715) K32(-14.605,-5.715) K33(-15.875,-5.715) K34(-17.145,-5.715) K35(-18.415,-5.715) K36(-19.685,-5.715) K37(-20.955,-5.715) K38(-22.225,-5.715) K39(-23.495,-5.715) K40(-24.765,-5.715)
DBV5
  rect 1.4x0.5 smd: 1(-1.1,0.95) 2(-1.1,0) 3(-1.1,-0.95) 4(1.1,-0.95) 5(1.1,0.95)
HDR_THVT_1X2_100_M
  rect 1.473x1.473 hole 0.965: 1(0,0)
  round 1.473 hole 0.965: 2(0,-2.54)
HDR_THVT_1X3_100_M
  rect 1.473x1.473 hole 0.965: 1(0,0)
  round 1.473 hole 0.965: 2(0,-2.54) 3(0,-5.08)
HEATSINK_270X270
  rect 6.858x6.858 smd: 1(0,0)
IND_0603
  rect 0.635x1.016 smd: 1(-0.635,0) 2(0.635,0)
IND_SM_XFL4015
  rect 1.2x3.5 smd: 1(-1.225,0) 2(1.225,0)
LED_1206
  rect 1.27x1.6 smd: 1(-1.524,0) 2(1.524,0)
MFG125_PLATED
  round 3.556 hole 3.175: 1(0,0)
PDFN_6_P35MM
  custom 0.045x0.045 smd: 1(-0.5,0.35) 2(-0.5,0) 3(-0.5,-0.35) 4(0.5,-0.35) 5(0.5,0) 6(0.5,0.35)
QFN20_RGW_P65PITCH
  custom 0.09x0.09 smd: 1(-2.607,1.3) 2(-2.607,0.65) 3(-2.607,0) 4(-2.607,-0.65) 5(-2.607,-1.3) 6(-1.3,-2.607) 7(-0.65,-2.607) 8(0,-2.607) 9(0.65,-2.607) 10(1.3,-2.607) 11(2.607,-1.3) 12(2.607,-0.65) 13(2.607,0) 14(2.607,0.65) 15(2.607,1.3) 16(1.3,2.607) 17(0.65,2.607) 18(0,2.607) 19(-0.65,2.607) 20(-1.3,2.607)
  rect 3.302x3.302 smd: 21(0,0)
QFN24_RGE_RTW_P5MM
  custom 0.076x0.076 smd: 1(-2.07,1.25) 2(-2.07,0.75) 3(-2.07,0.25) 4(-2.07,-0.25) 5(-2.07,-0.75) 6(-2.07,-1.25) 7(-1.25,-2.07) 8(-0.75,-2.07) 9(-0.25,-2.07) 10(0.25,-2.07) 11(0.75,-2.07) 12(1.25,-2.07) 13(2.07,-1.25) 14(2.07,-0.75) 15(2.07,-0.25) 16(2.07,0.25) 17(2.07,0.75) 18(2.07,1.25) 19(1.25,2.07) 20(0.75,2.07) 21(0.25,2.07) 22(-0.25,2.07) 23(-0.75,2.07) 24(-1.25,2.07)
  rect 2.54x2.54 smd: 25(0,0)
QFN40_RTA_RTB_RHA
  custom 0.076x0.076 smd: 1(-3.025,2.25) 2(-3.025,1.75) 3(-3.025,1.25) 4(-3.025,0.75) 5(-3.025,0.25) 6(-3.025,-0.25) 7(-3.025,-0.75) 8(-3.025,-1.25) 9(-3.025,-1.75) 10(-3.025,-2.25) 11(-2.25,-3.025) 12(-1.75,-3.025) 13(-1.25,-3.025) 14(-0.75,-3.025) 15(-0.25,-3.025) 16(0.25,-3.025) 17(0.75,-3.025) 18(1.25,-3.025) 19(1.75,-3.025) 20(2.25,-3.025) 21(3.025,-2.25) 22(3.025,-1.75) 23(3.025,-1.25) 24(3.025,-0.75) 25(3.025,-0.25) 26(3.025,0.25) 27(3.025,0.75) 28(3.025,1.25) 29(3.025,1.75) 30(3.025,2.25) 31(2.25,3.025) 32(1.75,3.025) 33(1.25,3.025) 34(0.75,3.025) 35(0.25,3.025) 36(-0.25,3.025) 37(-0.75,3.025) 38(-1.25,3.025) 39(-1.75,3.025) 40(-2.25,3.025)
  rect 4.572x4.572 smd: 41(0,0)
QFN_20_199X199_0P65MM
  rect 0.991x0.356 smd: 1(-2.4,1.3) 2(-2.4,0.65) 3(-2.4,0) 4(-2.4,-0.65) 5(-2.4,-1.3) 11(2.4,-1.3) 12(2.4,-0.65) 13(2.4,0) 14(2.4,0.65) 15(2.4,1.3)
  rect 0.356x0.991 smd: 6(-1.3,-2.4) 7(-0.65,-2.4) 8(0,-2.4) 9(0.65,-2.4) 10(1.3,-2.4) 16(1.3,2.4) 17(0.65,2.4) 18(0,2.4) 19(-0.65,2.4) 20(-1.3,2.4)
  rect 3.15x3.15 smd: 21(0,0)
QFN_64_360X360_0P50MM_PWRPAD
  oval 1.016x0.305 smd: 1(-4.58,3.753) 2(-4.58,3.252) 3(-4.58,2.752) 4(-4.58,2.252) 5(-4.58,1.751) 6(-4.58,1.251) 7(-4.58,0.751) 8(-4.58,0.25) 9(-4.58,-0.25) 10(-4.58,-0.751) 11(-4.58,-1.251) 12(-4.58,-1.751) 13(-4.58,-2.252) 14(-4.58,-2.752) 15(-4.58,-3.252) 16(-4.58,-3.753) 33(4.58,-3.753) 34(4.58,-3.252) 35(4.58,-2.752) 36(4.58,-2.252) 37(4.58,-1.751) 38(4.58,-1.251) 39(4.58,-0.751) 40(4.58,-0.25) 41(4.58,0.25) 42(4.58,0.751) 43(4.58,1.251) 44(4.58,1.751) 45(4.58,2.252) 46(4.58,2.752) 47(4.58,3.252) 48(4.58,3.753)
  oval 0.305x1.016 smd: 17(-3.753,-4.58) 18(-3.252,-4.58) 19(-2.752,-4.58) 20(-2.252,-4.58) 21(-1.751,-4.58) 22(-1.251,-4.58) 23(-0.751,-4.58) 24(-0.25,-4.58) 25(0.25,-4.58) 26(0.751,-4.58) 27(1.251,-4.58) 28(1.751,-4.58) 29(2.252,-4.58) 30(2.752,-4.58) 31(3.252,-4.58) 32(3.753,-4.58) 49(3.753,4.58) 50(3.252,4.58) 51(2.752,4.58) 52(2.252,4.58) 53(1.751,4.58) 54(1.251,4.58) 55(0.751,4.58) 56(0.25,4.58) 57(-0.25,4.58) 58(-0.751,4.58) 59(-1.251,4.58) 60(-1.751,4.58) 61(-2.252,4.58) 62(-2.752,4.58) 63(-3.252,4.58) 64(-3.753,4.58)
  rect 7.366x7.366 smd: 65(0,0)
QFN_72_10MMX10MM_0P50MM_PWRPAD
  oval 0.6x0.24 smd: 1(-4.9,4.25) 2(-4.9,3.75) 3(-4.9,3.25) 4(-4.9,2.75) 5(-4.9,2.25) 6(-4.9,1.75) 7(-4.9,1.25) 8(-4.9,0.75) 9(-4.9,0.25) 10(-4.9,-0.25) 11(-4.9,-0.75) 12(-4.9,-1.25) 13(-4.9,-1.75) 14(-4.9,-2.25) 15(-4.9,-2.75) 16(-4.9,-3.25) 17(-4.9,-3.75) 18(-4.9,-4.25) 37(4.9,-4.25) 38(4.9,-3.75) 39(4.9,-3.25) 40(4.9,-2.75) 41(4.9,-2.25) 42(4.9,-1.75) 43(4.9,-1.25) 44(4.9,-0.75) 45(4.9,-0.25) 46(4.9,0.25) 47(4.9,0.75) 48(4.9,1.25) 49(4.9,1.75) 50(4.9,2.25) 51(4.9,2.75) 52(4.9,3.25) 53(4.9,3.75) 54(4.9,4.25)
  oval 0.24x0.6 smd: 19(-4.25,-4.9) 20(-3.75,-4.9) 21(-3.25,-4.9) 22(-2.75,-4.9) 23(-2.25,-4.9) 24(-1.75,-4.9) 25(-1.25,-4.9) 26(-0.75,-4.9) 27(-0.25,-4.9) 28(0.25,-4.9) 29(0.75,-4.9) 30(1.25,-4.9) 31(1.75,-4.9) 32(2.25,-4.9) 33(2.75,-4.9) 34(3.25,-4.9) 35(3.75,-4.9) 36(4.25,-4.9) 55(4.25,4.9) 56(3.75,4.9) 57(3.25,4.9) 58(2.75,4.9) 59(2.25,4.9) 60(1.75,4.9) 61(1.25,4.9) 62(0.75,4.9) 63(0.25,4.9) 64(-0.25,4.9) 65(-0.75,4.9) 66(-1.25,4.9) 67(-1.75,4.9) 68(-2.25,4.9) 69(-2.75,4.9) 70(-3.25,4.9) 71(-3.75,4.9) 72(-4.25,4.9)
  rect 8.382x8.382 smd: 73(0,0)
QFN_RLT_7
  rect 1.016x0.305 smd: 1(-1.06,0.75) 2(-1.06,0.25) 3(-1.06,-0.25) 4(-1.06,-0.75)
  rect 1.829x0.356 smd: 5(0.66,-0.6) 6(0.66,0) 7(0.66,0.6)
SMA-MSSP-4848-EDGE_MICRO
  rect 1.397x0.483 smd: 1(0.318,0)
  rect 6.223x0.508 smd: 2(-2.095,2.095) 3(-2.095,-2.095)
SMA_THVT_312X312
  round 2.337 hole 1.575: 1(0,0)
  round 2.464 hole 1.702: 2(-2.54,2.54) 3(2.54,2.54) 4(2.54,-2.54) 5(-2.54,-2.54)
SMD_JUMPER_L_0402
  rect 0.508x0.508 smd: 1(-0.508,0) 2(0.508,0) 3(0.508,1.016)
SMP_B120
  rect 0.508x1.321 smd: 1(0,-3.1)
  custom 1.3x1.3 smd: 2(0,0)
SON_Q5B_8
  rect 1.372x0.711 smd: 1(-2.767,1.905) 2(-2.767,0.635) 3(-2.767,-0.635) 4(-2.767,-1.905) 5(2.767,-1.905) 6(2.767,-0.635) 7(2.767,0.635) 8(2.767,1.905)
SSOP_28_413X220_26
  rect 1.778x0.406 smd: 1(-3.625,4.225) 2(-3.625,3.575) 3(-3.625,2.925) 4(-3.625,2.275) 5(-3.625,1.625) 6(-3.625,0.975) 7(-3.625,0.325) 8(-3.625,-0.325) 9(-3.625,-0.975) 10(-3.625,-1.625) 11(-3.625,-2.275) 12(-3.625,-2.925) 13(-3.625,-3.575) 14(-3.625,-4.225) 15(3.625,-4.225) 16(3.625,-3.575) 17(3.625,-2.925) 18(3.625,-2.275) 19(3.625,-1.625) 20(3.625,-0.975) 21(3.625,-0.325) 22(3.625,0.325) 23(3.625,0.975) 24(3.625,1.625) 25(3.625,2.275) 26(3.625,2.925) 27(3.625,3.575) 28(3.625,4.225)
SW_SMVT_SPST_EVQPJX_2
  rect 2.007x1.6 smd: 1(-2.7,0) 2(2.7,0)
TANT_B
  rect 2.032x2.286 smd: 1(-1.524,0) 2(1.524,0)
TESTPOINT_62DIA
  round 2.337 hole 1.575: 1(0,0)
TFMR_5_150X150_50
  rect 1.651x0.762 smd: 1(1.587,1.27) 2(1.587,0) 3(1.587,-1.27) 4(-1.587,-1.27) 6(-1.587,1.27)
TP_THVT_060_RND
  round 1.575 hole 1.016: 1(0,0)
TSSOP14
  rect 1.651x0.33 smd: 1(-2.87,1.956) 2(-2.87,1.306) 3(-2.87,0.655) 4(-2.87,0.005) 5(-2.87,-0.645) 6(-2.87,-1.295) 7(-2.87,-1.946) 8(2.87,-1.946) 9(2.87,-1.295) 10(2.87,-0.645) 11(2.87,0.005) 12(2.87,0.655) 13(2.87,1.306) 14(2.87,1.956)
VCXO_6_CUSTOM
  rect 5.74x1.956 smd: 1(-3.81,2.54) 2(-3.81,0) 3(-3.81,-2.54) 4(3.81,-2.54) 5(3.81,0) 6(3.81,2.54)

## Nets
1.4V: C122.1 C126.1 C376.1 L2.2 R153.1 R154.1 R157.2 SJP3.1(PIN1) TP13.1(TP) U11.4(VOS) U17.5(IN1) U17.6(IN2) U17.7(IN3) U17.8(IN4)
3.3VUSB: C105.1 C369.2 U5.4(VCCIO) U5.17(3V3OUT) U13.14(VCCB)
5.0V_IN: F1.1 J8.1 Q1.5(D5) Q1.6(D6) Q1.7(D7) Q1.8(D8) TP17.1(TP) U15.5(VIN)
5VIN: C35.1 C121.1 C156.1 C172.1 C173.1 C183.1 C198.1 C203.1 C386.1 F1.2 Q1.1(S1) Q1.2(S2) Q1.3(S3) R95.1 R133.1 SJP4.1(PIN1) U4.13(EN) U4.15(IN2) U4.16(IN1) U9.13(EN) U9.15(IN2) U9.16(IN1) U11.1(EN) U11.7(IN) U12.13(EN) U12.15(IN2) U12.16(IN1) U14.1(EN) U14.7(IN) U17.10(BIAS) U18.7(IN)
+1.9V: FB20.3 SJP5.3(PIN3)
+2.2V: C184.1 C189.1 C190.1 C191.1 L1.2 R132.1 R136.1 SJP2.1(PIN1) TP15.1(TP) U14.4(VOS) U16.15(IN3) U16.16(IN2) U16.17(IN1)
+3.3V_LMX: C381.1 C382.1 C383.1 C384.1 C390.2 C392.1 C393.1 C396.1 C397.1 C398.2 C401.1 C402.2 FB15.2 R186.2 TP10.1(TP) U10.7(VCCDIG) U10.11(VCCCP) U10.15(VCCDIV) U10.21(VCCBUF) U10.26(VCCDBLR) U10.37(VCCVCO)
+3.3V_LMXRF: C379.1 C380.1 C408.1 C411.1 C428.1 FB14.2 R175.2 R176.2 R177.2 R178.2 R188.1 R189.1
+3.3VCLK: C160.1 C161.1 C162.1 C163.1 FB1.2 FB2.1 FB3.1 FB4.1 FB5.1 FB6.1 FB10.1 FB11.1 FB16.2 R71.1 R76.1 SJP1.3(PIN3) TP12.1(TP)
+4.5V: C11.1 C12.1 C65.1 C66.1 C76.1 C100.1 FB13.2 L4.1 L14.1 R2.1 R7.1 TP1.1(TP)
AVDD1.9V: C48.1 C49.1 C50.1 C51.1 C52.1 C53.1 C185.1 C186.1 C187.1 C188.1 FB20.1 R137.1 R166.1 R167.1 TP20.1(TP) U1.10(AVDD19#10) U1.16(AVDD19#16) U1.24(AVDD19#24) U1.31(AVDD19#31) U1.39(AVDD19#39) U1.45(AVDD19#45) U16.1(OUT1) U16.2(SNS) U16.19(OUT2) U16.20(OUT3)
AVDD1.15V: C37.1 C38.1 C39.1 C40.1 C41.1 C42.1 C43.1 C44.1 C45.1 C46.1 C47.1 C194.1 C195.1 C196.1 FB17.3 TP22.1(TP) U1.9(AVDD#9) U1.12(AVDD#12) U1.15(AVDD#15) U1.17(AVDD#17) U1.25(AVDD#25) U1.30(AVDD#30) U1.38(AVDD#38) U1.40(AVDD#40) U1.43(AVDD#43) U1.44(AVDD#44) U1.46(AVDD#46)
DVDD1.15V: C54.1 C55.1 C56.1 C57.1 C58.1 C59.1 C60.1 C377.1 C378.1 FB19.3 JP1.1(PIN1) R31.1 R33.1 R34.1 SJP5.1(PIN1) TP5.1(TP) U1.4(DVDD#4) U1.8(DVDD#8) U1.47(DVDD#47) U1.51(DVDD#51) U1.57(DVDD#57) U1.64(DVDD#64) U1.70(DVDD#70)
GND: C1.1 C11.2 C12.2 C25.2 C29.2 C32.2 C33.2 C34.2 C35.2 C36.2 C37.2 C38.2 C39.2 C40.2 C41.2 C42.2 C43.2 C44.2 C45.2 C46.2 C47.2 C48.2 C49.2 C50.2 C51.2 C52.2 C53.2 C54.2 C55.2 C56.2 C57.2 C58.2 C59.2 C60.2 C61.2 C62.2 C63.2 C64.2 C65.2 C66.2 C68.2 C72.2 C75.1 C76.2 C77.1 C78.1 C79.1 C80.1 C83.1 C86.1 C87.1 C88.1 C89.1 C90.1 C91.1 C92.1 C93.1 C94.1 C95.1 C96.2 C97.2 C98.1 C99.1 C100.2 C101.2 C102.2 C103.2 C104.2 C105.2 C114.1 C121.2 C122.2 C126.2 C156.2 C157.2 C158.2 C159.2 C160.2 C161.2 C162.2 C163.2 C166.2 C172.2 C173.2 C183.2 C184.2 C185.2 C186.2 C187.2 C188.2 C189.2 C190.2 C191.2 C194.2 C195.2 C196.2 C197.2 C198.2 C203.2 C204.2 C368.2 C369.1 C376.2 C377.2 C378.2 C379.2 C380.2 C381.2 C382.2 C383.2 C384.2 C385.2 C386.2 C387.2 C388.2 C389.2 C390.1 C391.1 C392.2 C393.2 C395.2 C396.2 C397.2 C398.1 C399.2 C400.1 C401.2 C402.1 C403.1 C404.1 C405.1 C406.1 C407.1 C408.2 C411.2 C420.2 C421.2 C428.2 C437.1 C438.1 C439.1 C440.1 D1.2(CATHODE) D2.2(CATHODE) D3.2(CATHODE) D4.2(CATHODE) D5.2(CATHODE) D6.2(CATHODE) D7.2(CATHODE) FB17.2 FB19.2 FB20.2 HS1.1 J1.2(SHIELD#2) J1.3(SHIELD#3) J2.2(SHIELD#2) J2.3(SHIELD#3) J3.2(SHIELD#2) J3.3(SHIELD#3) J4.2(SHIELD#2) J4.3(SHIELD#3) J5.2(SHIELD#2) J5.3(SHIELD#3) J6.2(SHIELD1) J7.2(GND#2) J7.3(GND#3) J7.4(GND#4) J7.5(GND#5) J8.2 J8.3 J9.2(GND#2) J9.3(GND#3) J9.4(GND#4) J9.5(GND#5) J10.A1 J10.A4 J10.A5 J10.A8 J10.A9 J10.A12 J10.A13 J10.A16 J10.A17 J10.A20 J10.A21 J10.A24 J10.A25 J10.A28 J10.A29 J10.A32 J10.A33 J10.A36 J10.A37 J10.A40 J10.B2 J10.B3 J10.B6 J10.B7 J10.B10 J10.B11 J10.B14 J10.B15 J10.B18 J10.B19 J10.B22 J10.B23 J10.B26 J10.B27 J10.B30 J10.B31 J10.B34 J10.B35 J10.B38 J10.B39 J10.C1 J10.C4 J10.C5 J10.C8 J10.C9 J10.C12 J10.C13 J10.C16 J10.C17 J10.C20 J10.C21 J10.C24 J10.C25 J10.C28 J10.C29 J10.C32 J10.C33 J10.C36 J10.C38 J10.C40 J10.D2 J10.D3 J10.D6 J10.D7 J10.D10 J10.D13 J10.D16 J10.D19 J10.D22 J10.D25 J10.D28 J10.D37 J10.D39 J10.E1 J10.E4 J10.E5 J10.E8 J10.E11 J10.E14 J10.E17 J10.E20 J10.E23 J10.E26 J10.E29 J10.E32 J10.E35 J10.E38 J10.E40 J10.F2 J10.F3 J10.F6 J10.F9 J10.F12 J10.F15 J10.F18 J10.F21 J10.F24 J10.F27 J10.F30 J10.F33 J10.F36 J10.F39 J10.G1 J10.G4 J10.G5 J10.G8 J10.G11 J10.G14 J10.G17 J10.G20 J10.G23 J10.G26 J10.G29 J10.G32 J10.G35 J10.G38 J10.G40 J10.H3 J10.H6 J10.H9 J10.H12 J10.H15 J10.H18 J10.H21 J10.H24 J10.H27 J10.H30 J10.H33 J10.H36 J10.H39 J10.J1 J10.J4 J10.J5 J10.J8 J10.J11 J10.J14 J10.J17 J10.J20 J10.J23 J10.J26 J10.J29 J10.J32 J10.J35 J10.J38 J10.J40 J10.K2 J10.K3 J10.K6 J10.K9 J10.K12 J10.K15 J10.K18 J10.K21 J10.K24 J10.K27 J10.K30 J10.K33 J10.K36 J10.K39 J11.5(GND) J11.6(GND1) J11.7(GND2) J11.8(GND3) J11.9(GND4) J13.2(GND#2) J13.3(GND#3) J13.4(GND#4) J13.5(GND#5) JP1.3(PIN3) JP2.1 JP3.2(PIN2) JP4.2 JP5.2 MT1.1 MT2.1 R3.2 R8.2 R11.1 R12.1 R13.1 R14.1 R32.2 R35.2 R47.2 R50.2 R51.2 R52.2 R53.2 R54.2 R55.2 R58.2 R59.2 R63.2 R64.2 R67.2 R68.2 R69.2 R70.2 R73.2 R74.2 R77.2 R78.2 R81.2 R82.2 R89.2 R96.1 R124.1 R125.1 R126.1 R127.1 R134.2 R138.1 R139.1 R140.1 R141.1 R145.2 R147.2 R151.2 R152.2 R155.2 R168.2 R169.2 R170.1 R171.1 R172.1 R173.1 R174.2 R179.1 R180.2 R181.2 R187.1 R192.1 SJP1.1(PIN1) SJP2.3(PIN3) SJP3.3(PIN3) SJP4.3(PIN3) T5.6(PRI DOT) T6.2(SECONDARY_CT) T6.4(PRIMARY) TP6.1(TP) TP11.1(TP) TP14.1(TP) TP18.1(TP) TP19.1(TP) TP21.1(TP) U1.3(DGND#3) U1.18(AGND#18) U1.23(AGND#23) U1.26(AGND#26) U1.29(AGND#29) U1.32(AGND#32) U1.37(AGND#37) U1.52(DGND#52) U1.60(DGND#60) U1.67(DGND#67) U1.73(THERMALPAD) U2.3(VS-#3) U2.4(VS-#4) U2.7(VS-#7) U2.8(VS-#8) U2.12(VS-#12) U2.15(VS-#15) U2.16(VS-#16) U2.19(VS-#19) U2.23(VS-#23) U2.24(VS-#24) U2.25(GND) U3.65(DAP) U4.7(GND) U4.21(PWRPAD) U5.7(GND#7) U5.18(GND#18) U5.21(GND#21) U5.25(AGND) U5.26(TEST) U7.2(GND) U8.2(GND) U9.7(GND) U9.21(PWRPAD) U10.2(GND#2) U10.4(GND#4) U10.6(GND#6) U10.13(GND#13) U10.14(GND#14) U10.25(GND#25) U10.31(GND#31) U10.34(GND#34) U10.39(GND#39) U10.40(NC4) U10.41(PWRPAD) U11.5(GND) U12.7(GND) U12.21(PWRPAD) U13.7(GND) U14.5(GND) U15.2(GND) U16.8(GND1) U16.18(GND2) U16.21(PWRPAD) U17.12(GND) U17.21(PWRPAD) U18.5(GND) Y1.3(GND)
P3.3VCLK: C157.1 C158.1 C159.1 FB16.1 U12.1(OUT1) U12.3(SENSE) U12.20(OUT2)
P3.3VLMX: C385.1 C388.1 C389.1 FB14.1 FB15.1 U9.1(OUT1) U9.3(SENSE) U9.20(OUT2)
P4.5V: C62.1 C63.1 C64.1 FB13.1 U4.1(OUT1) U4.3(SENSE) U4.20(OUT2)
V1: JP3.1(PIN1) R188.2 U7.1(V1) U8.1(V1)
V2: JP3.3(PIN3) R189.2 U7.5(V2) U8.5(V2)
+VSA: C32.1 C34.1 L14.2 U2.11(VS+#11)
+VSB: C25.1 C29.1 L4.2 U2.20(VS+#20)
A_IN_M: C5.1 J2.1(CENTER)
A_IN_P: C4.1 J1.1(CENTER)
ADC_CLK: C28.1 J5.1(CENTER)
ADC_CLKM: C430.2 R26.1 U1.28(CLKINM)
ADC_CLKP: C429.2 R26.2 U1.27(CLKINP)
ADC_SCLK: U1.6(SCLK) U13.2(A1)
ADC_SDIO: U1.5(SDATA) U13.3(A2)
ADC_SDO: U1.11(SDOUT) U13.4(A3)
ADC_SEN: R34.2 U1.7(SEN) U13.5(A4)
AINM: C3.2 L13.2 U1.41(INAM)
AINP: C3.1 L7.2 U1.42(INAP)
B_IN_M: C111.1 J4.1(CENTER)
B_IN_P: C110.1 J3.1(CENTER)
BINM: C6.2 L12.2 U1.14(INBM)
BINP: C6.1 L11.2 U1.13(INBP)
CE: JP2.2 R186.1 U10.1(CE)
CLK-IN: R56.1 R57.2 R59.1 R191.1 T6.6(PRIMARY_DOT)
CLK_LAO_0M: J10.G7 R79.2
CLK_LAO_0P: J10.G6 R75.2
CLKIN1_N: C74.2 C75.2 U3.35(CLKIN1N/FBCLKINN/FINN)
CLKIN1_P: C73.2 U3.34(CLKIN1P/FBCLKINP/FINP)
CLKINN: C74.1 R60.2 T6.3(SECONDARY)
CLKINP: C73.1 R55.1 R56.2 R60.1 T6.1(SECONDARY_DOT)
CLKLA_0M: R78.1 R79.1 U3.63(DCLKOUT12N)
CLKLA_0P: R75.1 R77.1 U3.62(DCLKOUT12P)
CLKM: C9.2 C432.2
CLKP: C8.2 C431.2
CMA: C1.2 R2.2 R3.1 U2.21(CMA)
CMB: C114.2 R7.2 R8.1 U2.10(CMB)
CP1: C68.1 C70.1 U3.32(CPOUT1) Y1.1(VC)
CP2: C71.1 C72.1 U3.46(CPOUT2)
CPOUT: C394.1 C395.1 R182.1 U10.12(CPOUT)
DA0_M: C14.1 U1.62(DA0M)
DA0_P: C13.1 U1.61(DA0P)
DA0M: C14.2 J10.B13
DA0P: C13.2 J10.B12
DA1_M: C16.1 U1.59(DA1M)
DA1_P: C15.1 U1.58(DA1P)
DA1M: C16.2 J10.A15
DA1P: C15.2 J10.A14
DA2_M: C18.1 U1.56(DA2M)
DA2_P: C17.1 U1.55(DA2P)
DA2M: C18.2 J10.B17
DA2P: C17.2 J10.B16
DA3_M: C20.1 U1.54(DA3M)
DA3_P: C19.1 U1.53(DA3P)
DA3M: C20.2 J10.A19
DA3P: C19.2 J10.A18
DB0_M: C22.1 U1.65(DB0M)
DB0_P: C21.1 U1.66(DB0P)
DB0M: C22.2 J10.A11
DB0P: C21.2 J10.A10
DB1_M: C24.1 U1.68(DB1M)
DB1_P: C23.1 U1.69(DB1P)
DB1M: C24.2 J10.C7
DB1P: C23.2 J10.C6
DB2_M: C27.1 U1.71(DB2M)
DB2_P: C26.1 U1.72(DB2P)
DB2M: C27.2 J10.A7
DB2P: C26.2 J10.A6
DB3_M: C31.1 U1.1(DB3M)
DB3_P: C30.1 U1.2(DB3P)
DB3M: C31.2 J10.A3
DB3P: C30.2 J10.A2
DCLKOUT10N: C171.1 R151.1 U3.55(DCLKOUT10N)
DCLKOUT10P: C170.1 R152.1 U3.54(DCLKOUT10P)
ENA: JP4.1 U2.22(ENA)
ENB: JP5.1 U2.9(ENB)
FMC_CTRL1: J10.C26 R165.1
FMC_CTRL2: J10.C27 R164.1
FPGA_JESD_CLKM: C69.2 J10.D5
FPGA_JESD_CLKP: C67.2 J10.D4
FPGA_JESD_SYSREFM: J10.G10 R49.2
FPGA_JESD_SYSREFP: J10.G9 R48.2
GPIO1: TP3.1(TP) U1.19(GPIO1)
GPIO2: TP7.1(TP) U1.63(GPIO2)
GTXCLKM: C69.1 R52.1 U3.2(DCLKOUT0N)
GTXCLKP: C67.1 R53.1 U3.1(DCLKOUT0P)
INA+: C4.2 R1.1 U2.5(INB+)
INA-: C5.2 R194.1 U2.6(INB-)
INB+: C110.2 R6.1 U2.2(INA+)
INB-: C111.2 R193.1 U2.1(INA-)
JESD_SYSREFM: R49.1 R50.1 U3.4(SDCLKOUT1N)
JESD_SYSREFP: R48.1 R51.1 U3.3(SDCLKOUT1P)
LMK LOCKED: D3.1(ANODE) R86.1
LMK_CLKIN: J7.1(CENTER) R57.1 R58.1
LMK_CSB: U3.18(\\C\S\) U5.6(D7)
LMK_SCLK: U3.19(SCK) U5.1(D0) U10.16(SCK) U13.13(B1)
LMK_SDIO: U3.20(SDIO) U5.5(D1) U10.17(SDI) U13.12(B2)
LMK_SDO: U3.5(RESET) U5.10(D6)
LMX_CLKB: C412.2 R191.2 R192.2
LMX_CLKM: C410.2 C432.1 U8.3(RF1)
LMX_CLKP: C409.2 C431.1 U7.3(RF1)
LMX_CSB: U5.9(D5) U10.24(CSB)
LMX_OSCM: C418.2 U10.9(OSCINM)
LMX_OSCP: C419.2 U10.8(OSCINP)
LMX_SDO: R184.2 U5.2(D4)
OSCINN: C85.2 C86.2 U3.44(OSCINN)
OSCINP: C82.2 C83.2 U3.43(OSCINP)
OSCN: C84.2 C85.1 R76.2 R82.1
OSCOUTN: C419.1 R180.1 U3.41(OSCOUTN)
OSCOUTP: C418.1 R181.1 U3.40(OSCOUTP)
OSCP: C81.2 C82.1 R71.2 R74.1
OUTA+: R4.1 U2.13(OUTB+)
OUTA-: R5.1 U2.14(OUTB-)
OUTB+: R9.1 U2.18(OUTA+)
OUTB-: R10.1 U2.17(OUTA-)
PDN: JP1.2(PIN2) U1.50(PDN)
PLL2 LOCKED: D4.1(ANODE) R87.1
RESET: R35.1 SW1.2 U1.48(RESET)
RFOUTBM: C413.2 J6.1(CENTER) R187.2
SCAN_EN: R31.2 R32.1 U1.49(SCAN_EN)
STAT 0: D1.1(ANODE) R84.1
STAT 1: D2.1(ANODE) R85.1
SYNC: TP16.1(TP) U3.6(SYNC)
SYNCBM: J10.G13 R166.2 R168.1 U1.36(SYNCBM)
SYNCBP: J10.G12 R167.2 R169.1 U1.35(SYNCBP)
SYSREF+: R65.1 R67.1 U3.13(SDCLKOUT3P)
SYSREF-: R66.1 R68.1 U3.14(SDCLKOUT3N)
SYSREFM: R29.1 R66.2 R69.1 U1.34(SYSREFM)
SYSREFP: R29.2 R65.2 R70.1 U1.33(SYSREFP)
TA+: C435.1 R4.2
TA-: C436.1 R5.2
TAA+: C2.1 L5.2 L7.1
